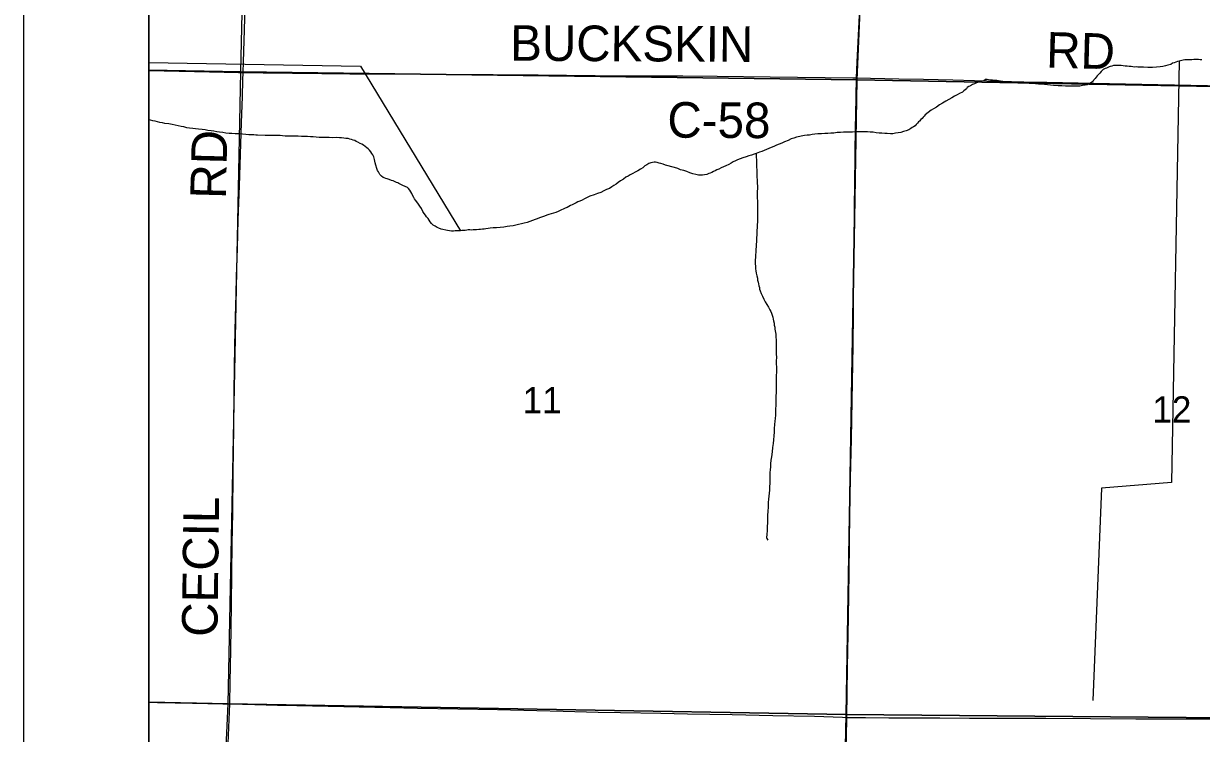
# Model space of a CAD drawing. Extents: x 2.4 to 73.1, y 4.5 to 25.6.
# Drawn here: x 29.397 to 30.338, y 23.653 to 24.22 of the extents above; entities that cross this region are included whole.
import ezdxf

# ---------------------------------------------------------------- set-up
doc = ezdxf.new("R2010")
doc.units = 0
for name, color, linetype in [('GM_X_County_Road', 7, 'Continuous'), ('GM_X_County_Road_Text', 7, 'Continuous'), ('GM_X_Interchange_Ramps', 7, 'Continuous'), ('GM_X_Minor_River', 7, 'Continuous'), ('GM_X_Section', 7, 'Continuous'), ('GM_X_Section_Text', 7, 'Continuous'), ('GM_X_Township_Road', 7, 'Continuous'), ('GM_X_Township_Road_Text', 7, 'Continuous'), ('GM_X_US_Shield', 7, 'Continuous'), ('SH_Cut_Line', 7, 'Continuous'), ('SH_Data', 7, 'Continuous')]:
    doc.layers.add(name, color=color, linetype=linetype)

msp = doc.modelspace()

# ---------------------------------------------------------------- linework, layer by layer
at = {"layer": 'GM_X_County_Road'}
for points in [[(30.06292, 24.17656), (30.06338, 24.18934), (30.06468, 24.21604), (30.06599, 24.24243)], [(29.49738, 24.18238), (29.54604, 24.18138), (29.56904, 24.18087), (29.57278, 24.1808)], [(29.57278, 24.1808), (29.58893, 24.18051), (29.63556, 24.17993), (29.65794, 24.17977), (29.68684, 24.17974), (29.74249, 24.17934), (29.77265, 24.17922), (29.8084, 24.1789), (29.85409, 24.17839), (29.87989, 24.1782), (29.92403, 24.17805), (29.95139, 24.17788), (29.99397, 24.17743), (30.01573, 24.17724), (30.05988, 24.17661), (30.06292, 24.17656)], [(30.05508, 23.66578), (30.05574, 23.70575), (30.05632, 23.74584), (30.05686, 23.78097), (30.05719, 23.80428), (30.05756, 23.82883), (30.05807, 23.8568), (30.05888, 23.88787), (30.05939, 23.91895), (30.06021, 23.96278), (30.0604, 23.98889), (30.06054, 24.01158), (30.06092, 24.04049), (30.06135, 24.07467), (30.06155, 24.09053), (30.06184, 24.1157), (30.06209, 24.13715), (30.06218, 24.14678), (30.06292, 24.17656)], [(30.06292, 24.17656), (30.09655, 24.1759), (30.11645, 24.17553), (30.13975, 24.17501), (30.15716, 24.17453), (30.19662, 24.1735), (30.21496, 24.17304), (30.265, 24.17206), (30.30353, 24.17119), (30.34331, 24.17033), (30.37781, 24.16958), (30.39553, 24.1693), (30.43718, 24.16841), (30.50368, 24.16693), (30.52357, 24.16653), (30.53663, 24.16629), (30.55154, 24.166), (30.55774, 24.16607), (30.56299, 24.16635), (30.5676, 24.16683), (30.57095, 24.16739), (30.57549, 24.16835), (30.57714, 24.16869)], [(30.04255, 23.16611), (30.04259, 23.16911), (30.04277, 23.18185), (30.04323, 23.19862), (30.04409, 23.2294), (30.04436, 23.24275), (30.04494, 23.26388), (30.04548, 23.2906), (30.0468, 23.34499), (30.04706, 23.35959), (30.04777, 23.38071), (30.04852, 23.41428), (30.04897, 23.43448), (30.04982, 23.46586), (30.05076, 23.50284), (30.05134, 23.52521), (30.05208, 23.55411), (30.05314, 23.59015), (30.05389, 23.6234), (30.05472, 23.6498), (30.05508, 23.66578)]]:
    msp.add_lwpolyline(points, dxfattribs=at)
at = {"layer": 'GM_X_Interchange_Ramps'}
msp.add_lwpolyline([(29.49738, 24.68879), (29.49738, 21.67933)], dxfattribs=at)
at = {"layer": 'GM_X_Minor_River'}
for points in [[(29.49738, 24.18894), (29.66647, 24.18581), (29.74653, 24.05441)], [(30.33067, 24.19103), (30.32839, 24.19107), (30.32667, 24.1909), (30.32515, 24.19093), (30.32382, 24.19076), (30.32286, 24.19039), (30.32172, 24.19022), (30.32057, 24.18986), (30.31923, 24.1895), (30.3179, 24.18914), (30.31656, 24.18859), (30.31522, 24.18824), (30.31387, 24.18731), (30.31158, 24.18677), (30.30967, 24.18624), (30.30757, 24.1857), (30.30548, 24.18535), (30.30262, 24.18502), (30.29919, 24.18488), (30.29558, 24.18494), (30.29216, 24.18499), (30.28969, 24.18503), (30.28759, 24.18507), (30.28627, 24.18528), (30.28455, 24.18511), (30.2836, 24.18532), (30.28228, 24.18553), (30.28076, 24.18575), (30.27905, 24.18577), (30.27734, 24.18599), (30.27582, 24.1862), (30.2743, 24.18642), (30.27297, 24.18644), (30.27183, 24.18646), (30.26803, 24.18633), (30.26669, 24.18578), (30.26554, 24.18561), (30.26458, 24.18524), (30.26363, 24.18488), (30.26267, 24.18432), (30.26152, 24.18396), (30.25999, 24.18323), (30.25903, 24.18248), (30.25825, 24.18154), (30.25728, 24.18042), (30.25612, 24.1793), (30.25515, 24.17817), (30.25419, 24.17705), (30.25341, 24.17592), (30.25244, 24.17499), (30.25186, 24.17405), (30.2505, 24.17274), (30.24839, 24.17144), (30.24705, 24.17108), (30.24553, 24.17073), (30.24343, 24.17038), (30.24114, 24.17004), (30.23867, 24.16989), (30.23581, 24.16993), (30.23296, 24.16998), (30.22992, 24.16984), (30.22688, 24.17007), (30.22384, 24.17031), (30.22023, 24.17056), (30.21795, 24.17079), (30.21548, 24.17102), (30.21301, 24.17125), (30.21073, 24.17147), (30.20826, 24.17151), (30.2058, 24.17174), (30.20333, 24.17197), (30.20085, 24.17201), (30.19858, 24.17224), (30.19648, 24.17227), (30.19459, 24.17249), (30.19173, 24.17253), (30.18965, 24.17276), (30.18736, 24.17279), (30.18508, 24.17302), (30.18319, 24.17324), (30.17787, 24.17389), (30.17635, 24.17411), (30.17503, 24.17432), (30.17351, 24.17453), (30.17161, 24.17475), (30.1699, 24.17478), (30.16838, 24.17499), (30.16724, 24.1752), (30.16591, 24.17522), (30.16457, 24.1743), (30.16227, 24.17357), (30.16074, 24.17303), (30.15883, 24.17249), (30.15711, 24.17175), (30.15539, 24.17121), (30.15385, 24.17029), (30.15251, 24.16955), (30.15136, 24.16881), (30.15058, 24.16787), (30.14865, 24.16619), (30.14749, 24.16507)], [(30.32057, 24.18986), (30.31444, 23.85335), (30.25864, 23.84892), (30.25174, 23.67942)], [(30.33885, 24.1909), (30.33751, 24.19092), (30.336, 24.19113), (30.3341, 24.19116), (30.33239, 24.19119), (30.33067, 24.19103)], [(30.14749, 24.16507), (30.14519, 24.16397), (30.14328, 24.16305), (30.14117, 24.16194), (30.13905, 24.16064), (30.13656, 24.15916), (30.13407, 24.15787), (30.13157, 24.15639), (30.12907, 24.15491), (30.12676, 24.15324), (30.12446, 24.15195), (30.12235, 24.15065), (30.11773, 24.14692), (30.11676, 24.14599), (30.11598, 24.14505), (30.11521, 24.14411), (30.11424, 24.14318), (30.11327, 24.14206), (30.11231, 24.14131), (30.11154, 24.14037), (30.11057, 24.13944), (30.10979, 24.13831), (30.10845, 24.13757), (30.1073, 24.13683), (30.10614, 24.13609), (30.10461, 24.13516), (30.1025, 24.13425), (30.1004, 24.13371), (30.0983, 24.13299), (30.0962, 24.13264), (30.09391, 24.13229), (30.09181, 24.13195), (30.08991, 24.13198), (30.08725, 24.13202), (30.08535, 24.13224), (30.08307, 24.13247), (30.08098, 24.1325), (30.07851, 24.13273), (30.07624, 24.13315), (30.07376, 24.13318), (30.07149, 24.13341), (30.06921, 24.13345), (30.06711, 24.13348), (30.06483, 24.13352), (30.06255, 24.13336), (30.0595, 24.13322), (30.05722, 24.13307), (30.05475, 24.13311), (30.05246, 24.13314), (30.04999, 24.13299), (30.04732, 24.13284), (30.04485, 24.1325), (30.04237, 24.13235), (30.0399, 24.1322), (30.03743, 24.13224), (30.03495, 24.1319), (30.0319, 24.13176), (30.02962, 24.13161), (30.02733, 24.13126), (30.02523, 24.13091), (30.02333, 24.13076), (30.02123, 24.13041), (30.01493, 24.12918), (30.01283, 24.12845), (30.01054, 24.12773), (30.00824, 24.12644), (30.00518, 24.12554), (30.00326, 24.12443), (30.00096, 24.1237), (29.99886, 24.12279), (29.99675, 24.12187), (29.99464, 24.12095), (29.99273, 24.12003), (29.991, 24.1193), (29.98909, 24.11857), (29.98718, 24.11784), (29.98526, 24.11711), (29.98278, 24.1162), (29.98106, 24.11566), (29.97895, 24.11493), (29.97685, 24.11421), (29.97456, 24.11348), (29.97207, 24.11276), (29.96997, 24.11185), (29.96786, 24.11112), (29.96614, 24.1102), (29.96441, 24.10947), (29.96269, 24.10854), (29.96095, 24.10724), (29.95847, 24.10633), (29.95655, 24.10541), (29.95464, 24.10468), (29.95291, 24.10376), (29.95119, 24.10303), (29.94984, 24.10229), (29.9485, 24.10174), (29.94735, 24.101), (29.94601, 24.10045), (29.94486, 24.10009), (29.94333, 24.09935), (29.94142, 24.099)], [(29.60035, 24.13043), (29.59845, 24.13047), (29.59617, 24.1305), (29.5937, 24.13054), (29.59046, 24.13059), (29.58438, 24.13069), (29.58286, 24.13071), (29.58134, 24.13093), (29.57944, 24.13096), (29.57735, 24.13118), (29.57507, 24.13141), (29.57241, 24.13164), (29.56994, 24.13187), (29.56633, 24.13192), (29.56386, 24.13215), (29.56158, 24.13219), (29.55911, 24.13242), (29.55665, 24.13284), (29.55399, 24.13307), (29.55171, 24.13349), (29.54944, 24.1339), (29.54716, 24.13413), (29.54469, 24.13455), (29.54242, 24.13496), (29.54014, 24.13538), (29.5371, 24.13562), (29.53482, 24.13584), (29.53254, 24.13607), (29.53008, 24.13649), (29.5278, 24.13671), (29.52553, 24.13732), (29.52325, 24.13774), (29.52098, 24.13815), (29.51851, 24.13876), (29.51605, 24.13918), (29.51339, 24.13979), (29.51036, 24.14022), (29.50827, 24.14063), (29.50638, 24.14104), (29.50448, 24.14145), (29.50259, 24.14186), (29.50069, 24.14227), (29.4988, 24.14268), (29.49738, 24.14313)], [(29.74653, 24.05441), (29.7452, 24.05443), (29.74425, 24.05426), (29.7433, 24.05427), (29.74216, 24.05429), (29.74082, 24.05412), (29.7393, 24.05415), (29.73778, 24.05436), (29.73608, 24.05458), (29.73096, 24.0558), (29.72926, 24.0564), (29.72775, 24.05718), (29.72624, 24.05815), (29.72473, 24.05894), (29.72342, 24.06029), (29.7223, 24.06164), (29.72137, 24.06279), (29.72063, 24.06413), (29.71932, 24.06548), (29.71839, 24.06683), (29.71746, 24.06817), (29.71635, 24.0699), (29.71525, 24.0722), (29.71394, 24.07412), (29.71283, 24.07565), (29.71153, 24.07757), (29.71041, 24.07892), (29.70966, 24.07988), (29.70911, 24.08103), (29.70819, 24.08294), (29.70745, 24.08429), (29.7069, 24.08562), (29.70597, 24.08697), (29.70504, 24.08831), (29.7041, 24.0889), (29.70222, 24.08988), (29.70051, 24.09047), (29.69882, 24.09145), (29.69731, 24.09224), (29.69636, 24.09263), (29.69523, 24.09303), (29.69429, 24.09361), (29.69278, 24.09421), (29.69126, 24.09461), (29.68937, 24.0954), (29.68786, 24.0958), (29.68672, 24.0962), (29.68559, 24.0966), (29.68464, 24.097), (29.68333, 24.09797), (29.68202, 24.09951), (29.68146, 24.10047), (29.68091, 24.10161), (29.68017, 24.10257), (29.67962, 24.1041), (29.67891, 24.10696), (29.67836, 24.10868), (29.67783, 24.11135), (29.67711, 24.11345), (29.67637, 24.11498), (29.67563, 24.11613), (29.6747, 24.11748), (29.67377, 24.11882), (29.67265, 24.11998), (29.67171, 24.12076), (29.67039, 24.12173), (29.66908, 24.1227), (29.66776, 24.12348), (29.66625, 24.12426), (29.66455, 24.12524), (29.66323, 24.12583), (29.6621, 24.12642), (29.66077, 24.12682), (29.65945, 24.12722), (29.65812, 24.12762), (29.65661, 24.12802), (29.6549, 24.12824), (29.65319, 24.12846), (29.65148, 24.12867), (29.64977, 24.1287), (29.64749, 24.12893), (29.64426, 24.12879), (29.6416, 24.12883), (29.63875, 24.12888), (29.63608, 24.12892), (29.63361, 24.12896), (29.63114, 24.12919), (29.62886, 24.12941), (29.62658, 24.12945), (29.62411, 24.12968), (29.62183, 24.12972), (29.61955, 24.12975), (29.6167, 24.12999), (29.61461, 24.13002), (29.61233, 24.13006), (29.61043, 24.13009), (29.60833, 24.13012), (29.60643, 24.12996), (29.60434, 24.13018), (29.60244, 24.1304), (29.60035, 24.13043)], [(29.98278, 24.1162), (29.98353, 24.09206), (29.9837, 24.09035), (29.98367, 24.08845), (29.98343, 24.08542), (29.98339, 24.08314), (29.98354, 24.08067), (29.98369, 24.0782), (29.98366, 24.07592), (29.98363, 24.07402), (29.98379, 24.0723), (29.98376, 24.0704), (29.98373, 24.06851), (29.9837, 24.06661), (29.98366, 24.06433), (29.98362, 24.06186), (29.98357, 24.05882), (29.98335, 24.05673), (29.98332, 24.05484), (29.98329, 24.05275), (29.98326, 24.05104), (29.98304, 24.04914), (29.98301, 24.04743), (29.98298, 24.04553), (29.98276, 24.04364), (29.98254, 24.04174), (29.98251, 24.03984), (29.98247, 24.03737), (29.98224, 24.0351), (29.98221, 24.03301), (29.98199, 24.03111), (29.98196, 24.0294), (29.98194, 24.02788), (29.98211, 24.02655), (29.98209, 24.02541), (29.98226, 24.02408), (29.98242, 24.02237), (29.98277, 24.02046), (29.98312, 24.01856), (29.98366, 24.01646), (29.98382, 24.01494), (29.98418, 24.01341), (29.98454, 24.01208), (29.98489, 24.01055), (29.98525, 24.00922), (29.98542, 24.00769), (29.98597, 24.00636), (29.98669, 24.00425), (29.9878, 24.00215), (29.98891, 23.99985), (29.98982, 23.99756), (29.99242, 23.99353), (29.99316, 23.99238), (29.99371, 23.99123), (29.99445, 23.98988), (29.995, 23.98855), (29.99555, 23.98702), (29.9959, 23.98549), (29.99626, 23.98397), (29.99662, 23.98244), (29.99697, 23.98073), (29.99713, 23.97902), (29.99749, 23.97749), (29.99765, 23.97597), (29.99782, 23.97464), (29.99818, 23.9733), (29.99835, 23.97178), (29.99851, 23.97026), (29.99849, 23.96893), (29.99866, 23.96778), (29.99863, 23.96589), (29.99859, 23.96323), (29.99875, 23.96113), (29.99871, 23.95886), (29.99867, 23.9562), (29.99881, 23.95335), (29.99877, 23.9505), (29.99873, 23.94803), (29.99888, 23.94575), (29.99884, 23.94347), (29.99881, 23.94119), (29.99877, 23.9391), (29.99874, 23.93701), (29.99869, 23.93416), (29.99866, 23.9317), (29.99862, 23.92923), (29.99858, 23.92714), (29.99855, 23.92486), (29.99851, 23.92277), (29.99848, 23.92068), (29.99844, 23.91859), (29.99842, 23.91669), (29.99838, 23.91461), (29.99816, 23.91252), (29.99811, 23.90967), (29.99807, 23.9072), (29.99784, 23.90455)], [(29.94142, 24.099), (29.9399, 24.09884), (29.93819, 24.09886), (29.93648, 24.09889), (29.93439, 24.0993), (29.93212, 24.09991), (29.92966, 24.10071), (29.9272, 24.1017), (29.92493, 24.10249), (29.92228, 24.1031), (29.92001, 24.10409), (29.91755, 24.10489), (29.91036, 24.1069), (29.90847, 24.1075), (29.90657, 24.1081), (29.90506, 24.10851), (29.90354, 24.10891), (29.90222, 24.10912), (29.90108, 24.10914), (29.89974, 24.10897), (29.8986, 24.1088), (29.89687, 24.10807), (29.89534, 24.10714), (29.8938, 24.10622), (29.89207, 24.10472), (29.89015, 24.10361), (29.88803, 24.10232), (29.88612, 24.10121), (29.8842, 24.1001), (29.88209, 24.09918), (29.88036, 24.09807), (29.87863, 24.09715), (29.87671, 24.09566), (29.87421, 24.09437), (29.87248, 24.09307), (29.87075, 24.09176), (29.86902, 24.09065), (29.86729, 24.08954), (29.86537, 24.08824), (29.86307, 24.08733), (29.86096, 24.08622), (29.85847, 24.08512), (29.85579, 24.08421), (29.85312, 24.08312), (29.84986, 24.08203), (29.84775, 24.08092), (29.84546, 24.07982), (29.84354, 24.0789), (29.84182, 24.07817), (29.84009, 24.07743), (29.83875, 24.0767), (29.83722, 24.07596), (29.83568, 24.07522), (29.83434, 24.07468), (29.833, 24.07394), (29.83165, 24.07301), (29.83012, 24.07246), (29.82859, 24.07173), (29.82725, 24.07118), (29.8261, 24.07063), (29.82438, 24.06989), (29.82265, 24.06916), (29.81711, 24.06735), (29.81539, 24.06681), (29.81348, 24.06608), (29.81118, 24.06536), (29.80965, 24.06481), (29.80774, 24.06408), (29.80601, 24.06335), (29.80391, 24.06262), (29.80181, 24.0619), (29.7997, 24.06117), (29.79741, 24.06045), (29.79512, 24.05991), (29.79283, 24.05938), (29.79054, 24.05903), (29.78863, 24.05849), (29.78577, 24.05816), (29.78367, 24.05781), (29.78119, 24.05728), (29.77815, 24.05714), (29.77529, 24.05681), (29.77262, 24.05666), (29.77015, 24.05651), (29.76843, 24.05616), (29.76672, 24.05599), (29.76538, 24.05582), (29.76405, 24.05566), (29.76234, 24.05549), (29.761, 24.05532), (29.75929, 24.05516), (29.75796, 24.05518), (29.75663, 24.0552), (29.75529, 24.05503), (29.75396, 24.05506), (29.75263, 24.05508), (29.75149, 24.0549), (29.75015, 24.05474), (29.74882, 24.05476), (29.74749, 24.05459), (29.74653, 24.05441)], [(29.99784, 23.90455), (29.99761, 23.90227), (29.99738, 23.89962), (29.99714, 23.89658), (29.99709, 23.89354), (29.99619, 23.88463), (29.99576, 23.88141), (29.99532, 23.878), (29.99487, 23.87382), (29.99445, 23.87117), (29.99422, 23.86833), (29.99399, 23.86586), (29.99395, 23.86339), (29.99372, 23.86131), (29.99369, 23.85922), (29.99366, 23.85713), (29.99362, 23.85485), (29.99358, 23.85257), (29.99335, 23.85011), (29.99331, 23.84726), (29.99308, 23.84479), (29.99285, 23.84252), (29.99262, 23.84005), (29.99239, 23.8374), (29.99216, 23.83512), (29.99213, 23.83304), (29.9921, 23.83114), (29.99207, 23.82962), (29.99185, 23.82791), (29.99182, 23.82582), (29.99179, 23.82373), (29.99174, 23.8207), (29.99152, 23.8188), (29.99148, 23.81652), (29.99145, 23.81424), (29.99123, 23.81273), (29.99121, 23.81121), (29.991, 23.80988), (29.99099, 23.80969), (29.99099, 23.80931), (29.99117, 23.80874), (29.9919, 23.80721)]]:
    msp.add_lwpolyline(points, dxfattribs=at)
at = {"layer": 'GM_X_Section'}
for points in [[(29.5823, 24.68727), (30.08467, 24.67635), (30.06297, 24.17498), (29.57092, 24.18131)], [(30.08467, 24.67635), (30.5844, 24.66605), (30.57744, 24.17117), (30.5773, 24.16549), (30.06297, 24.17498)], [(29.57092, 24.18131), (30.06297, 24.17498), (30.0546, 23.66801), (29.56071, 23.67665)], [(30.06297, 24.17498), (30.5773, 24.16549), (30.56753, 23.66348), (30.0546, 23.66801)], [(29.56071, 23.67665), (30.0546, 23.66801), (30.04412, 23.1681), (29.53795, 23.17834)], [(30.0546, 23.66801), (30.56753, 23.66348), (30.56745, 23.66026), (30.55466, 23.16723), (30.55431, 23.16022), (30.04412, 23.1681)]]:
    msp.add_lwpolyline(points, close=True, dxfattribs=at)
at = {"layer": 'GM_X_Township_Road'}
for points in [[(29.57278, 24.1808), (29.573, 24.18948), (29.57387, 24.21464), (29.57533, 24.2631), (29.57583, 24.28205), (29.57666, 24.31436), (29.57712, 24.32741), (29.57766, 24.34294), (29.57814, 24.36127), (29.57939, 24.41439), (29.58019, 24.44826), (29.58077, 24.47716), (29.58144, 24.50543), (29.58197, 24.53931), (29.58221, 24.55204), (29.58236, 24.5682), (29.58255, 24.58747), (29.58278, 24.60798), (29.58305, 24.62631), (29.5833, 24.64061), (29.58389, 24.67199), (29.58406, 24.68687)], [(29.5622, 23.67658), (29.56251, 23.6942), (29.56285, 23.71938), (29.56346, 23.75543), (29.56377, 23.78123), (29.56409, 23.80454), (29.56449, 23.8294), (29.56484, 23.86079), (29.56534, 23.89716), (29.56553, 23.92637), (29.56614, 23.96243), (29.56672, 23.98573), (29.56721, 24.00375), (29.56757, 24.01774), (29.5682, 24.04042), (29.56895, 24.06309), (29.56991, 24.09043), (29.57146, 24.14076), (29.5722, 24.16157), (29.57259, 24.17462), (29.57278, 24.1808)], [(29.49738, 23.67794), (29.50443, 23.6778), (29.5324, 23.67729), (29.55664, 23.67666), (29.5622, 23.67658)], [(29.53909, 23.17764), (29.53918, 23.18157), (29.53942, 23.1881), (29.54254, 23.25361), (29.54357, 23.27596), (29.5446, 23.29707), (29.54581, 23.3216), (29.54777, 23.35978), (29.54897, 23.38182), (29.54994, 23.40448), (29.55118, 23.43368), (29.5524, 23.46256), (29.55368, 23.4905), (29.55532, 23.52652), (29.55887, 23.60104), (29.5601, 23.62587), (29.56176, 23.66407), (29.5622, 23.67658)], [(29.5622, 23.67658), (29.58212, 23.676), (29.60014, 23.67549), (29.61568, 23.67529), (29.64086, 23.67486), (29.69028, 23.67375), (29.71203, 23.67326), (29.74436, 23.67275), (29.77606, 23.67201), (29.80745, 23.67132), (29.82858, 23.6708), (29.85655, 23.67009), (29.87427, 23.66976), (29.90659, 23.66922), (29.92772, 23.66869), (29.96347, 23.66801), (29.9961, 23.66736), (30.02936, 23.66675), (30.05172, 23.66592), (30.05508, 23.66578)], [(30.05508, 23.66578), (30.05669, 23.66572), (30.07005, 23.66567), (30.0887, 23.66552), (30.09865, 23.66543), (30.12943, 23.6654), (30.15305, 23.66526), (30.16766, 23.66521), (30.19253, 23.66524), (30.21398, 23.6651), (30.24973, 23.66482), (30.2861, 23.66473), (30.30475, 23.66467), (30.32558, 23.66461), (30.36444, 23.66457)]]:
    msp.add_lwpolyline(points, dxfattribs=at)
at = {"layer": 'GM_X_US_Shield'}
for points in [[(29.49738, 24.68888), (29.49738, 24.18278), (29.57092, 24.18131), (29.5823, 24.68727)], [(29.49738, 24.18278), (29.49738, 23.67785), (29.56071, 23.67665), (29.57092, 24.18131)], [(29.49738, 23.67785), (29.49738, 23.17918), (29.53795, 23.17834), (29.56071, 23.67665)]]:
    msp.add_lwpolyline(points, close=True, dxfattribs=at)
at = {"layer": 'SH_Cut_Line'}
msp.add_lwpolyline([(36.29738, 24.78522), (29.49738, 24.78522), (29.49738, 21.67933)], dxfattribs=at)
at = {"layer": 'SH_Data'}
msp.add_line((29.39738, 24.88522), (29.39738, 17.88522), dxfattribs=at)
msp.add_lwpolyline([(29.49738, 24.78522), (36.29738, 24.78522), (36.29738, 17.98522), (29.49738, 17.98522)], close=True, dxfattribs=at)

# ---------------------------------------------------------------- texts
at = {"layer": 'GM_X_County_Road_Text'}
for s, rotation, p in [('BUCKSKIN', 359.73081, (29.7861, 24.19023)), ('RD', 358.51748, (30.21411, 24.1848)), ('C-58', 359.65668, (29.91167, 24.12885))]:
    msp.add_text(s, height=0.028409, rotation=rotation, dxfattribs=at).set_placement(p)
at = {"layer": 'GM_X_Section_Text'}
for s, p in [('11', (29.79612, 23.90865)), ('12', (30.29924, 23.90131))]:
    msp.add_text(s, height=0.020928, rotation=0.00001, dxfattribs=at).set_placement(p)
at = {"layer": 'GM_X_Township_Road_Text'}
for s, rotation, p in [('RD', 88.53766, (29.5589, 24.07968)), ('CECIL', 89.28986, (29.55223, 23.72999))]:
    msp.add_text(s, height=0.028409, rotation=rotation, dxfattribs=at).set_placement(p)

doc.saveas('drawing.dxf')
